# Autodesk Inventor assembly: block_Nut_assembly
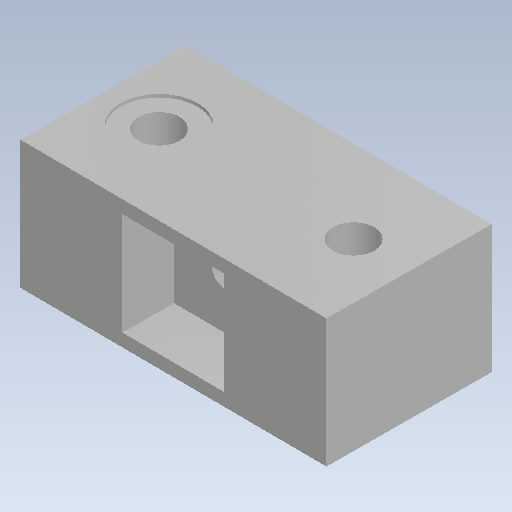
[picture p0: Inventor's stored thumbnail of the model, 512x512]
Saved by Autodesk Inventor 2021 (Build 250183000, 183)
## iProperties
Created: 2026-10
Part Number: block_Nut_assembly
Document SubType Name: Assembly
Designer: hp
Author: hp
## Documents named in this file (3)
- C:\Users\hp\Downloads\block_Nut_assembly.iam
- C:\Users\hp\Downloads\nut_Block_with_Bearing.ipt
- C:\Users\hp\Downloads\8mm_Bearing.ipt
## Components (2 placed, 2 different names)
1. nut_Block_with_Bearing:1
2. 8mm_Bearing:1
